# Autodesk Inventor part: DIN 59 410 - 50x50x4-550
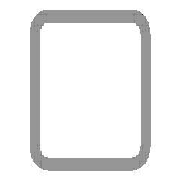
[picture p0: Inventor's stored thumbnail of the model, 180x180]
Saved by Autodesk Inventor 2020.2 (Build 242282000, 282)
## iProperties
Manager: www.cadconsulting.pl
Company: Fabian Stasiak CAD Consulting
Created: 2015-01
Part Number: DIN 59 410 - 50x50x4-550
Material: Stal, miękka
Description: Rurki stalowe o przekroju kwadratowym formowane na gorąco
Document SubType Name: Modellieren
Standard: DIN
Designer: F.Stasiak
Standards Organization: DIN
Language: pl-PL
Size Designation: 50x50x4
Categories: <MemberInstance><Categories><Category DisplayName="Kształtowniki konstrukcyjne" InternalName="089c4875-fa83-4c05-b084-43b9cc11f5ed" Mnemonic="GRDR"><CategoryPar
Stock Number: 50x50x4
Density: 7.85 g/cm^3
Appearance: Częściowo polerowana
Mass: 2999.78 g
Surface Area: 1924.59 cm^2
Volume: 382.138 cm^3
Catalog Web Link: www.expertbooks.pl
_CCFamilyMember: 40
_CCFamilyDisplayName: DIN 59410 (Kwadrat) - Rurki stalowe o przekroju kwadratowym formowane na gorąco
_FrameMemberDoc: Frame Member File
_Version: 15.0.0
_GetPNFromCC: 1
G_W: 50,000 mm
G_H: 50,000 mm
+FBEA3164-9981-4DC4-B1BA-C4CF80C86FD2+CUTDETAIL1: Wytnij
+17E44ED1-A3A4-4A84-B59F-30D898EEE13D+CUTDETAIL2: Wytnij
G_L: 550,000 mm
IsCustomPart: 1
Author: F.Stasiak
Subject: Zbiór ćwiczeń. Autodesk Inventor 2020. Kurs Professional
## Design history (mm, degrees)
node "Płaszczyzna początkowa"
node "Płaszczyzna końcowa"
sketch "Szkic"
  geometry: L1 (-17, 25)-(17, 25); L2 (25, 17)-(25, -17); L3 (17, -25)-(-17, -25); L4 (-25, -17)-(-25, 17); L5 (-37.32, 0)-(37.32, 0) reference; L6 (0, -37.32)-(0, 37.32) reference; L7 (-17, 21)-(17, 21); L8 (21, 17)-(21, -17); L9 (17, -21)-(-17, -21); L10 (-21, -17)-(-21, 17); A1 r 8 centre (-17, 17) between (-17, 25) and (-25, 17); A2 r 8 centre (17, 17) between (25, 17) and (17, 25); A3 r 8 centre (17, -17) between (17, -25) and (25, -17); A4 r 8 centre (-17, -17) between (-25, -17) and (-17, -25); A5 r 4 centre (-17, 17) between (-17, 21) and (-21, 17); A6 r 4 centre (17, 17) between (21, 17) and (17, 21); A7 r 4 centre (17, -17) between (17, -21) and (21, -17); A8 r 4 centre (-17, -17) between (-21, -17) and (-17, -21); 3 further points
  constraints: 16 end point, 16 point on circle, 8 centre point, 8 tangent, 6 point on line, 4 parallel, 3 equal radius, 3 perpendicular, 1 horizontal, 7 other
  dimensions: "b" = 50 distance of point (-25, 25) point (25, 25); "msp_r" = 8 radius of A1 (= 2 x ParT); "d8" = 25 distance between parallel lines of L4 L6 (= d9); "d9" = 25 distance between parallel lines of L3 L5 (= 0.5 x b); "d10" = 4 distance between parallel lines of L3 L9 (= ParT)
extrude "Bryła" new body sketch "Szkic" taper "d4" = 0 deg; stored distance "NLG" = 10
node "Driven Length"
  sketch "Sketch2"
    geometry: L1 (0, 0)-(10, 0) reference
    constraints: 2 end point, 1 horizontal
  workplane "Work Plane3"
  sketch "Sketch3"
    geometry: L1 (-2, 25)-(12, 25) reference; L2 (-2, 575)-(12, 575) reference
    dimensions: "d14" = 550 distance between parallel lines of L1 L2 (derived)
node "Płaszczyzna konstrukcyjna4"
feature "Podział1"
node "Płaszczyzna konstrukcyjna5"
feature "Podział2"
body "Solid1"
other parameters: "ParT" = 4, "G_OFFSET_START" = -25 [user parameter; used in 1 equation term], "G_OFFSET_END" = -25 [user parameter; used in 1 equation term], "d11" = 25 (= -G_OFFSET_START), "d12" = 575 (= G_OFFSET_END + B_L), "G_L" = 550 (= d14) [user parameter], "d13" = 90 deg
